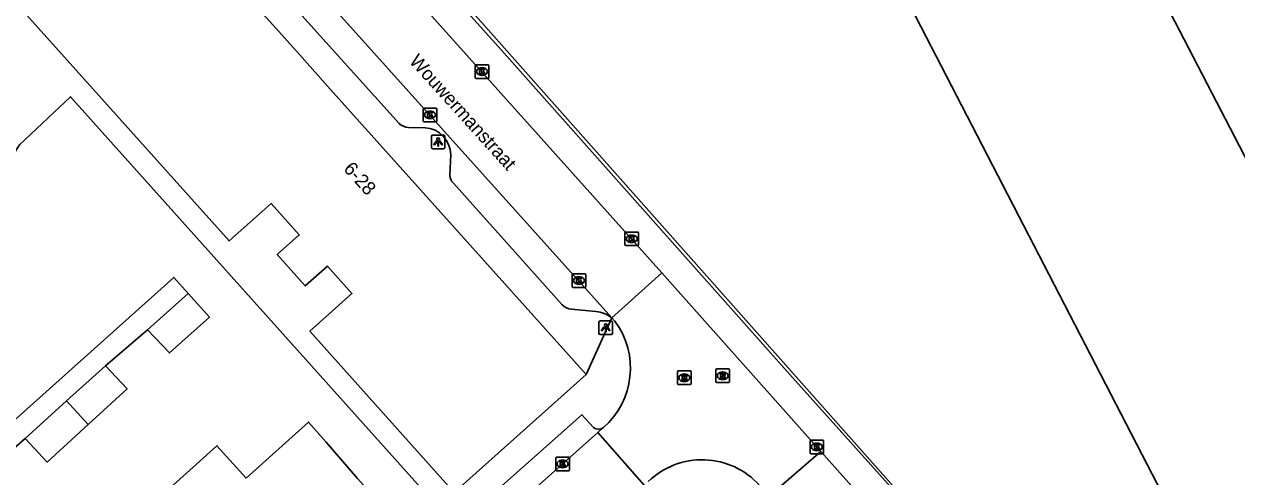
# Model space of a CAD drawing. Extents: x 162172 to 163187, y 382874 to 383684.
# Drawn here: x 162825.2 to 162914.3, y 383600.5 to 383633.8 of the extents above; entities that cross this region are included whole.
import ezdxf

# ---------------------------------------------------------------- set-up
doc = ezdxf.new("R2010")
doc.units = 0
for name, color, linetype in [('IMGEO_Hek', 7, 'Continuous'), ('IMGEO_Kolk', 7, 'Continuous'), ('IMGEO_Lichtpunt', 7, 'Continuous'), ('IMGEO_Openbare_ruimte_label', 7, 'Continuous'), ('IMGEO_Pand', 7, 'Continuous'), ('IMGEO_Pand_nummerreeks', 7, 'Continuous'), ('IMGEO_Rijbaan_lokaal_open', 7, 'Continuous'), ('IMGEO_Rioolput', 7, 'Continuous'), ('IMGEO_Voetpad_open', 7, 'Continuous')]:
    doc.layers.add(name, color=color, linetype=linetype)

msp = doc.modelspace()

# ---------------------------------------------------------------- linework, layer by layer
at = {"layer": 'IMGEO_Hek'}
msp.add_lwpolyline([(162837.735, 383657.749), (162909.951, 383576.274), (162910.848, 383575.766), (162911.823, 383575.526), (162912.895, 383575.736)], dxfattribs=at)
at = {"layer": 'IMGEO_Kolk'}
for p, q in [((162858.372, 383629.884), (162858.372, 383630.736)), ((162858.447, 383630.81), (162859.299, 383630.81)), ((162858.86, 383630.59), (162858.885, 383630.59)), ((162859.373, 383630.736), (162859.373, 383629.884)), ((162859.299, 383629.81), (162858.447, 383629.81)), ((162858.883, 383630.03), (162858.858, 383630.03)), ((162854.554, 383626.698), (162854.554, 383627.55)), ((162854.629, 383627.624), (162855.481, 383627.624)), ((162855.555, 383627.55), (162855.555, 383626.698)), ((162855.481, 383626.624), (162854.629, 383626.624)), ((162855.065, 383626.844), (162855.04, 383626.844)), ((162855.042, 383627.404), (162855.067, 383627.404)), ((162869.371, 383617.588), (162869.371, 383618.44)), ((162869.446, 383618.514), (162870.298, 383618.514)), ((162869.882, 383617.734), (162869.857, 383617.734)), ((162869.859, 383618.294), (162869.884, 383618.294)), ((162870.372, 383618.44), (162870.372, 383617.588)), ((162870.298, 383617.514), (162869.446, 383617.514)), ((162865.498, 383614.519), (162865.498, 383615.371)), ((162865.573, 383615.445), (162866.425, 383615.445)), ((162865.986, 383615.225), (162866.011, 383615.225)), ((162866.499, 383615.371), (162866.499, 383614.519)), ((162866.425, 383614.445), (162865.573, 383614.445)), ((162866.009, 383614.665), (162865.984, 383614.665)), ((162882.965, 383602.285), (162882.965, 383603.137)), ((162883.04, 383603.211), (162883.892, 383603.211)), ((162883.453, 383602.991), (162883.478, 383602.991)), ((162883.966, 383603.137), (162883.966, 383602.285)), ((162864.291, 383601.038), (162864.291, 383601.89)), ((162864.366, 383601.964), (162865.218, 383601.964)), ((162864.779, 383601.744), (162864.804, 383601.744)), ((162865.292, 383601.89), (162865.292, 383601.038)), ((162883.892, 383602.211), (162883.04, 383602.211)), ((162883.476, 383602.431), (162883.451, 383602.431)), ((162865.218, 383600.964), (162864.366, 383600.964)), ((162864.802, 383601.184), (162864.777, 383601.184))]:
    msp.add_line(p, q, dxfattribs=at)
for points in [[(162858.372, 383629.884), (162858.372, 383630.736)], [(162858.447, 383630.81), (162859.299, 383630.81)], [(162858.693, 383630.51), (162858.816, 383630.51), (162858.816, 383630.359), (162858.946, 383630.51), (162859.11, 383630.51), (162858.964, 383630.359), (162859.117, 383630.11), (162858.965, 383630.11), (162858.88, 383630.274), (162858.816, 383630.207), (162858.816, 383630.11), (162858.693, 383630.11), (162858.693, 383630.51)], [(162859.373, 383630.736), (162859.373, 383629.884)], [(162859.299, 383629.81), (162858.447, 383629.81)], [(162854.554, 383626.698), (162854.554, 383627.55)], [(162854.629, 383627.624), (162855.481, 383627.624)], [(162855.555, 383627.55), (162855.555, 383626.698)], [(162855.481, 383626.624), (162854.629, 383626.624)], [(162854.875, 383627.324), (162854.998, 383627.324), (162854.998, 383627.173), (162855.128, 383627.324), (162855.292, 383627.324), (162855.146, 383627.173), (162855.299, 383626.924), (162855.147, 383626.924), (162855.062, 383627.088), (162854.998, 383627.021), (162854.998, 383626.924), (162854.875, 383626.924), (162854.875, 383627.324)], [(162869.371, 383617.588), (162869.371, 383618.44)], [(162869.446, 383618.514), (162870.298, 383618.514)], [(162869.692, 383618.214), (162869.815, 383618.214), (162869.815, 383618.063), (162869.945, 383618.214), (162870.109, 383618.214), (162869.963, 383618.063), (162870.116, 383617.814), (162869.964, 383617.814), (162869.879, 383617.978), (162869.815, 383617.911), (162869.815, 383617.814), (162869.692, 383617.814), (162869.692, 383618.214)], [(162870.372, 383618.44), (162870.372, 383617.588)], [(162870.298, 383617.514), (162869.446, 383617.514)], [(162865.498, 383614.519), (162865.498, 383615.371)], [(162865.573, 383615.445), (162866.425, 383615.445)], [(162865.819, 383615.145), (162865.942, 383615.145), (162865.942, 383614.994), (162866.072, 383615.145), (162866.236, 383615.145), (162866.09, 383614.994), (162866.243, 383614.745), (162866.091, 383614.745), (162866.006, 383614.909), (162865.942, 383614.842), (162865.942, 383614.745), (162865.819, 383614.745), (162865.819, 383615.145)], [(162866.499, 383615.371), (162866.499, 383614.519)], [(162866.425, 383614.445), (162865.573, 383614.445)], [(162882.965, 383602.285), (162882.965, 383603.137)], [(162883.04, 383603.211), (162883.892, 383603.211)], [(162883.286, 383602.911), (162883.409, 383602.911), (162883.409, 383602.76), (162883.539, 383602.911), (162883.703, 383602.911), (162883.557, 383602.76), (162883.71, 383602.511), (162883.558, 383602.511), (162883.473, 383602.675), (162883.409, 383602.608), (162883.409, 383602.511), (162883.286, 383602.511), (162883.286, 383602.911)], [(162883.966, 383603.137), (162883.966, 383602.285)], [(162864.291, 383601.038), (162864.291, 383601.89)], [(162864.366, 383601.964), (162865.218, 383601.964)], [(162865.292, 383601.89), (162865.292, 383601.038)], [(162883.892, 383602.211), (162883.04, 383602.211)], [(162865.218, 383600.964), (162864.366, 383600.964)], [(162864.612, 383601.664), (162864.735, 383601.664), (162864.735, 383601.513), (162864.865, 383601.664), (162865.029, 383601.664), (162864.883, 383601.513), (162865.036, 383601.264), (162864.884, 383601.264), (162864.799, 383601.428), (162864.735, 383601.361), (162864.735, 383601.264), (162864.612, 383601.264), (162864.612, 383601.664)]]:
    msp.add_lwpolyline(points, dxfattribs=at)
for centre, start, end in [((162858.449, 383630.734), 91.55205, 178.44795), ((162858.449, 383630.734), 91.55205, 178.44795), ((162859.297, 383630.734), 1.55205, 88.44795), ((162859.297, 383630.734), 1.55205, 88.44795), ((162858.449, 383629.886), 181.55205, 268.44795), ((162858.449, 383629.886), 181.55205, 268.44795), ((162859.297, 383629.886), 271.55205, 358.44795), ((162859.297, 383629.886), 271.55205, 358.44795), ((162854.631, 383627.548), 91.55205, 178.44795), ((162854.631, 383627.548), 91.55205, 178.44795), ((162855.479, 383627.548), 1.55205, 88.44795), ((162855.479, 383627.548), 1.55205, 88.44795), ((162854.631, 383626.7), 181.55205, 268.44795), ((162854.631, 383626.7), 181.55205, 268.44795), ((162855.479, 383626.7), 271.55205, 358.44795), ((162855.479, 383626.7), 271.55205, 358.44795), ((162869.448, 383618.438), 91.55205, 178.44795), ((162869.448, 383618.438), 91.55205, 178.44795), ((162870.296, 383618.438), 1.55205, 88.44795), ((162870.296, 383618.438), 1.55205, 88.44795), ((162869.448, 383617.59), 181.55205, 268.44795), ((162869.448, 383617.59), 181.55205, 268.44795), ((162870.296, 383617.59), 271.55205, 358.44795), ((162870.296, 383617.59), 271.55205, 358.44795), ((162865.575, 383615.369), 91.55205, 178.44795), ((162865.575, 383615.369), 91.55205, 178.44795), ((162866.423, 383615.369), 1.55205, 88.44795), ((162866.423, 383615.369), 1.55205, 88.44795), ((162865.575, 383614.521), 181.55205, 268.44795), ((162865.575, 383614.521), 181.55205, 268.44795), ((162866.423, 383614.521), 271.55205, 358.44795), ((162866.423, 383614.521), 271.55205, 358.44795), ((162883.042, 383603.135), 91.55205, 178.44795), ((162883.042, 383603.135), 91.55205, 178.44795), ((162883.89, 383603.135), 1.55205, 88.44795), ((162883.89, 383603.135), 1.55205, 88.44795), ((162864.368, 383601.888), 91.55205, 178.44795), ((162864.368, 383601.888), 91.55205, 178.44795), ((162865.216, 383601.888), 1.55205, 88.44795), ((162865.216, 383601.888), 1.55205, 88.44795), ((162883.042, 383602.287), 181.55205, 268.44795), ((162883.042, 383602.287), 181.55205, 268.44795), ((162883.89, 383602.287), 271.55205, 358.44795), ((162883.89, 383602.287), 271.55205, 358.44795), ((162864.368, 383601.04), 181.55205, 268.44795), ((162864.368, 383601.04), 181.55205, 268.44795), ((162865.216, 383601.04), 271.55205, 358.44795), ((162865.216, 383601.04), 271.55205, 358.44795)]:
    msp.add_arc(centre, 0.0765, start, end, dxfattribs=at)
for centre, major_axis, ratio, start_param, end_param in [((162858.859, 383630.31), (-0.387, 0.002), 0.722429, 4.712389, 7.853982), ((162858.884, 383630.31), (-0.39, 0.002), 0.717154, 1.570796, 4.712389), ((162855.041, 383627.124), (-0.387, 0.002), 0.722429, 4.712389, 7.853982), ((162855.066, 383627.124), (-0.39, 0.002), 0.717154, 1.570796, 4.712389), ((162869.858, 383618.014), (-0.387, 0.002), 0.722429, 4.712389, 7.853982), ((162869.883, 383618.014), (-0.39, 0.002), 0.717154, 1.570796, 4.712389), ((162865.985, 383614.945), (-0.387, 0.002), 0.722429, 4.712389, 7.853982), ((162866.01, 383614.945), (-0.39, 0.002), 0.717154, 1.570796, 4.712389), ((162883.452, 383602.711), (-0.387, 0.002), 0.722429, 4.712389, 7.853982), ((162883.477, 383602.711), (-0.39, 0.002), 0.717154, 1.570796, 4.712389), ((162864.778, 383601.464), (-0.387, 0.002), 0.722429, 4.712389, 7.853982), ((162864.803, 383601.464), (-0.39, 0.002), 0.717154, 1.570796, 4.712389)]:
    msp.add_ellipse(centre, major_axis=major_axis, ratio=ratio, start_param=start_param, end_param=end_param, dxfattribs=at)
at = {"layer": 'IMGEO_Lichtpunt'}
for p, q in [((162855.155, 383625.542), (162855.155, 383624.735)), ((162855.155, 383625.542), (162855.155, 383624.735)), ((162856.057, 383625.637), (162855.249, 383625.637)), ((162856.057, 383625.637), (162855.249, 383625.637)), ((162856.151, 383624.735), (162856.151, 383625.542)), ((162856.151, 383624.735), (162856.151, 383625.542)), ((162855.249, 383624.641), (162856.057, 383624.641)), ((162855.249, 383624.641), (162856.057, 383624.641)), ((162867.458, 383611.878), (162867.458, 383611.071)), ((162867.458, 383611.878), (162867.458, 383611.071)), ((162868.36, 383611.973), (162867.552, 383611.973)), ((162868.36, 383611.973), (162867.552, 383611.973)), ((162868.454, 383611.071), (162868.454, 383611.878)), ((162868.454, 383611.071), (162868.454, 383611.878)), ((162867.552, 383610.977), (162868.36, 383610.977)), ((162867.552, 383610.977), (162868.36, 383610.977))]:
    msp.add_line(p, q, dxfattribs=at)
for points in [[(162855.529, 383625.206), (162855.568, 383625.178), (162855.38, 383624.916), (162855.342, 383624.943), (162855.529, 383625.206)], [(162855.631, 383625.158), (162855.678, 383625.158), (162855.678, 383624.836), (162855.631, 383624.836), (162855.631, 383625.158)], [(162855.741, 383625.178), (162855.779, 383625.205), (162855.966, 383624.943), (162855.927, 383624.915), (162855.741, 383625.178)], [(162867.832, 383611.542), (162867.871, 383611.514), (162867.683, 383611.252), (162867.645, 383611.279), (162867.832, 383611.542)], [(162867.934, 383611.494), (162867.981, 383611.494), (162867.981, 383611.172), (162867.934, 383611.172), (162867.934, 383611.494)], [(162868.044, 383611.514), (162868.082, 383611.541), (162868.269, 383611.279), (162868.23, 383611.251), (162868.044, 383611.514)]]:
    msp.add_lwpolyline(points, dxfattribs=at)
for centre in [(162855.654, 383625.34), (162867.957, 383611.676)]:
    msp.add_circle(centre, 0.0994, dxfattribs=at)
for centre, start, end in [((162855.249, 383625.542), 90, 180), ((162855.249, 383625.542), 90, 180), ((162856.057, 383625.542), 0, 90), ((162856.057, 383625.542), 0, 90), ((162855.249, 383624.735), 180, 270), ((162855.249, 383624.735), 180, 270), ((162856.057, 383624.735), 270, 0), ((162856.057, 383624.735), 270, 360), ((162867.552, 383611.878), 90, 180), ((162867.552, 383611.878), 90, 180), ((162868.36, 383611.878), 0, 90), ((162868.36, 383611.878), 0, 90), ((162867.552, 383611.071), 180, 270), ((162867.552, 383611.071), 180, 270), ((162868.36, 383611.071), 270, 0), ((162868.36, 383611.071), 270, 360)]:
    msp.add_arc(centre, 0.0946, start, end, dxfattribs=at)
at = {"layer": 'IMGEO_Pand'}
for points in [[(162903.848, 383642.115), (162907.362, 383635.264), (162908.733, 383635.998), (162929.815, 383595.307), (162914.889, 383587.573), (162890.357, 383635.092), (162903.848, 383642.115)], [(162866.531, 383608.046), (162849.883, 383626.617), (162847.728, 383629.021), (162845.652, 383631.337), (162843.499, 383633.738), (162841.788, 383635.647), (162839.637, 383638.046), (162838.423, 383639.401), (162835.743, 383637.307)], [(162825.009, 383634.943), (162840.291, 383617.86), (162843.376, 383620.62), (162845.446, 383618.306), (162843.829, 383616.86), (162845.894, 383614.551), (162847.511, 383615.998), (162849.314, 383613.982), (162846.229, 383611.222), (162853.503, 383603.091), (162856.838, 383599.366)], [(162837.28, 383613.997), (162838.848, 383612.252), (162835.929, 383609.631), (162834.297, 383611.319)], [(162834.297, 383611.319), (162837.28, 383613.997)], [(162828.358, 383606.114), (162831.229, 383608.674)], [(162831.229, 383608.674), (162832.804, 383606.977), (162829.938, 383604.354)], [(162856.838, 383599.366), (162866.531, 383608.046)], [(162825.317, 383603.332), (162828.358, 383606.114)], [(162828.358, 383606.114), (162829.938, 383604.354)], [(162829.938, 383604.354), (162826.927, 383601.598), (162825.317, 383603.332)], [(162841.538, 383600.414), (162846.137, 383604.542), (162847.425, 383603.056), (162849.73, 383600.398), (162853.389, 383596.32)], [(162841.538, 383600.414), (162839.401, 383602.795), (162834.937, 383598.787), (162837.074, 383596.405)]]:
    msp.add_lwpolyline(points, dxfattribs=at)
at = {"layer": 'IMGEO_Rijbaan_lokaal_open'}
for points in [[(162835.255, 383656.66), (162836.576, 383655.17), (162846.526, 383644.076), (162872.078, 383615.502)], [(162868.397, 383612.205), (162834.085, 383650.483)], [(162872.078, 383615.502), (162868.397, 383612.205)], [(162883.756, 383602.384), (162872.078, 383615.502)], [(162868.63, 383611.961), (162868.397, 383612.205)], [(162860.851, 383597.939), (162867.388, 383603.781)], [(162867.783, 383604.134), (162867.388, 383603.781)], [(162867.388, 383603.781), (162870.78, 383599.901)], [(162883.756, 383602.384), (162879.97, 383599.083)], [(162907.901, 383575.325), (162883.756, 383602.384)]]:
    msp.add_lwpolyline(points, dxfattribs=at)
for centre, radius, start, end in [((162863.984, 383608.504), 5.791, 311.00184, 36.64568), ((162875.036, 383596.109), 5.664, 41.88646, 134.19944)]:
    msp.add_arc(centre, radius, start, end, dxfattribs=at)
at = {"layer": 'IMGEO_Rioolput'}
for p, q in [((162873.232, 383607.375), (162873.232, 383608.227)), ((162873.307, 383608.301), (162874.159, 383608.301)), ((162873.72, 383608.081), (162873.745, 383608.081)), ((162874.233, 383608.227), (162874.233, 383607.375)), ((162876.045, 383607.52), (162876.045, 383608.372)), ((162876.12, 383608.446), (162876.972, 383608.446)), ((162876.533, 383608.226), (162876.558, 383608.226)), ((162877.046, 383608.372), (162877.046, 383607.52)), ((162874.159, 383607.301), (162873.307, 383607.301)), ((162873.743, 383607.521), (162873.718, 383607.521)), ((162876.972, 383607.446), (162876.12, 383607.446)), ((162876.556, 383607.666), (162876.531, 383607.666))]:
    msp.add_line(p, q, dxfattribs=at)
for points in [[(162873.232, 383607.375), (162873.232, 383608.227)], [(162873.307, 383608.301), (162874.159, 383608.301)], [(162873.821, 383607.999), (162873.569, 383608.001), (162873.569, 383607.601)], [(162873.747, 383607.92), (162873.693, 383607.92), (162873.693, 383607.839)], [(162874.233, 383608.227), (162874.233, 383607.375)], [(162876.045, 383607.52), (162876.045, 383608.372)], [(162876.12, 383608.446), (162876.972, 383608.446)], [(162876.634, 383608.144), (162876.382, 383608.146), (162876.382, 383607.746)], [(162876.382, 383607.746), (162876.506, 383607.746), (162876.506, 383607.908), (162876.517, 383607.908)], [(162876.56, 383608.065), (162876.506, 383608.065), (162876.506, 383607.984)], [(162876.506, 383607.984), (162876.558, 383607.984)], [(162877.046, 383608.372), (162877.046, 383607.52)], [(162874.159, 383607.301), (162873.307, 383607.301)], [(162873.569, 383607.601), (162873.693, 383607.601), (162873.693, 383607.763), (162873.704, 383607.763)], [(162873.693, 383607.839), (162873.745, 383607.839)], [(162873.751, 383607.734), (162873.822, 383607.601), (162873.962, 383607.601), (162873.897, 383607.727)], [(162876.972, 383607.446), (162876.12, 383607.446)], [(162876.564, 383607.879), (162876.635, 383607.746), (162876.775, 383607.746), (162876.71, 383607.872)]]:
    msp.add_lwpolyline(points, dxfattribs=at)
for centre, radius, start, end in [((162873.309, 383608.225), 0.0765, 91.55205, 178.44795), ((162873.309, 383608.225), 0.0765, 91.55205, 178.44795), ((162873.753, 383607.824), 0.0964, 77.00612, 93.18647), ((162873.767, 383607.881), 0.0378, 276.66336, 79.67722), ((162873.82, 383607.889), 0.109, 350.36119, 89.41601), ((162874.157, 383608.225), 0.0765, 1.55205, 88.44795), ((162874.157, 383608.225), 0.0765, 1.55205, 88.44795), ((162876.122, 383608.37), 0.0765, 91.55205, 178.44795), ((162876.122, 383608.37), 0.0765, 91.55205, 178.44795), ((162876.516, 383607.855), 0.0533, 26.02933, 88.69889), ((162876.542, 383608.173), 0.19, 274.7715, 282.96867), ((162876.566, 383607.969), 0.0964, 77.00612, 93.18647), ((162876.58, 383608.026), 0.0378, 276.66336, 79.67722), ((162876.633, 383608.034), 0.109, 350.36119, 89.41601), ((162876.631, 383608.034), 0.112, 277.58423, 350.98172), ((162876.615, 383607.819), 0.108, 29.51342, 73.79051), ((162876.97, 383608.37), 0.0765, 1.55205, 88.44795), ((162876.97, 383608.37), 0.0765, 1.55205, 88.44795), ((162873.309, 383607.377), 0.0765, 181.55205, 268.44795), ((162873.309, 383607.377), 0.0765, 181.55205, 268.44795), ((162873.703, 383607.71), 0.0533, 26.02933, 88.69889), ((162873.729, 383608.028), 0.19, 274.7715, 282.96867), ((162873.818, 383607.889), 0.112, 277.58423, 350.98172), ((162873.802, 383607.674), 0.108, 29.51342, 73.79051), ((162874.157, 383607.377), 0.0765, 271.55205, 358.44795), ((162874.157, 383607.377), 0.0765, 271.55205, 358.44795), ((162876.122, 383607.522), 0.0765, 181.55205, 268.44795), ((162876.122, 383607.522), 0.0765, 181.55205, 268.44795), ((162876.97, 383607.522), 0.0765, 271.55205, 358.44795), ((162876.97, 383607.522), 0.0765, 271.55205, 358.44795)]:
    msp.add_arc(centre, radius, start, end, dxfattribs=at)
for centre, major_axis, ratio, start_param, end_param in [((162873.719, 383607.801), (-0.387, 0.002), 0.722429, 4.712389, 7.853982), ((162873.744, 383607.801), (-0.39, 0.002), 0.717154, 1.570796, 4.712389), ((162876.532, 383607.946), (-0.387, 0.002), 0.722429, 4.712389, 7.853982), ((162876.557, 383607.946), (-0.39, 0.002), 0.717154, 1.570796, 4.712389)]:
    msp.add_ellipse(centre, major_axis=major_axis, ratio=ratio, start_param=start_param, end_param=end_param, dxfattribs=at)
at = {"layer": 'IMGEO_Voetpad_open'}
for points in [[(162837.594, 383657.15), (162860.297, 383631.879), (162881.252, 383608.295), (162909.981, 383576.237)], [(162852.797, 383626.499), (162842.061, 383638.426)], [(162855.634, 383598.303), (162828.636, 383628.454), (162824.889, 383624.929), (162815.65, 383610.257), (162814.957, 383604.925), (162819.337, 383600.047), (162836.228, 383615.172), (162837.28, 383613.997)], [(162854.688, 383626.184), (162853.472, 383626.194)], [(162856.501, 383622.694), (162856.578, 383624.206)], [(162864.754, 383613.167), (162856.769, 383622.108)], [(162867.235, 383612.673), (162865.447, 383612.831)], [(162866.531, 383608.046), (162868.397, 383612.205)], [(162834.297, 383611.319), (162831.229, 383608.674)], [(162860.851, 383597.939), (162859.673, 383599.258), (162866.207, 383605.08), (162867.069, 383604.145)], [(162825.317, 383603.332), (162822.235, 383600.627)]]:
    msp.add_lwpolyline(points, dxfattribs=at)
for centre, radius, start, end in [((162853.568, 383627.305), 1.115, 226.28252, 265.08564), ((162854.544, 383624.154), 2.035, 1.45897, 85.93443), ((162857.401, 383622.751), 0.902, 183.64804, 225.50479), ((162865.533, 383613.89), 1.063, 222.88625, 265.38104), ((162867.06, 383610.562), 2.119, 50.86679, 85.2586), ((162867.433, 383604.563), 0.554, 228.95802, 309.2767)]:
    msp.add_arc(centre, radius, start, end, dxfattribs=at)

# ---------------------------------------------------------------- texts
at = {"layer": 'IMGEO_Openbare_ruimte_label'}
msp.add_text('Wouwermanstraat', height=1, rotation=312.08093, dxfattribs=at).set_placement((162853.47, 383631.023))
at = {"layer": 'IMGEO_Pand_nummerreeks'}
msp.add_text('6-28', height=1, rotation=311.91165, dxfattribs=at).set_placement((162848.645, 383623.121))

doc.saveas('drawing.dxf')
